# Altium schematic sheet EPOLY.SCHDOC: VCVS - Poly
size A; DocumentNumber: 1; SheetNumber: 1; SheetTotal: 1
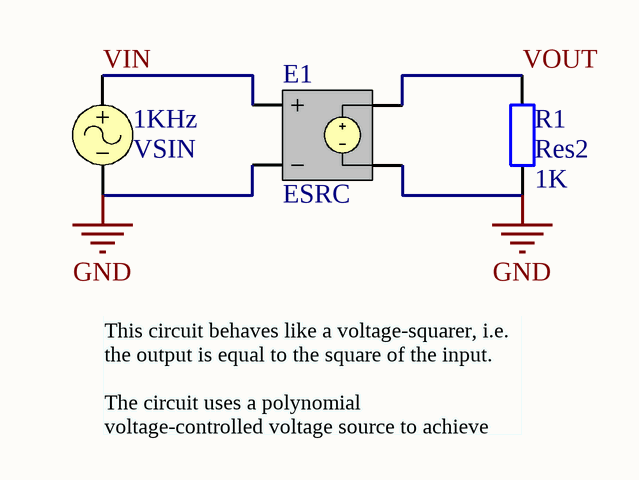
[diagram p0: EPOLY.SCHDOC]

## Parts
1KHz  VSIN
E1  ESRC
R1  Res2  value 1K  [AXIAL-0.4]

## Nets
GND: 1KHz.2 E1.2(NC-) E1.4(N-) R1.1
VIN: 1KHz.1 E1.1(NC+)
VOUT: E1.3(N+) R1.2

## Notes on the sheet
- This circuit behaves like a voltage-squarer, i.e. the output is equal to the square of the input.
  The circuit uses a polynomial voltage-controlled voltage source to achieve this result.

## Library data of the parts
1KHz = VSIN: Sinusoidal Voltage Source; Note: PCB Footprint - Not required
E1 = ESRC: Voltage Controlled Voltage Source; Note: PCB Footprint - Not required; Sim Note: Enter gain into gain field
R1 = Res2: Resistor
